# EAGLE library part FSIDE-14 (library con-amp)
AMP connector
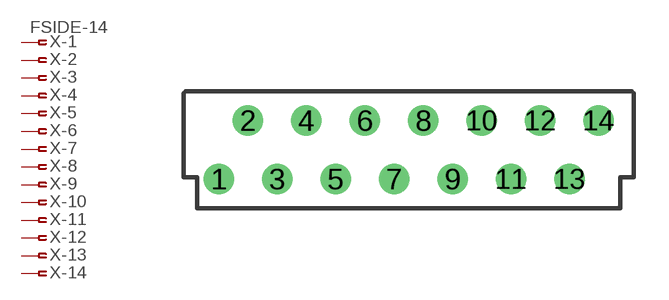
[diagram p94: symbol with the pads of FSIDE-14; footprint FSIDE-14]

Designator prefix X; gates -1=PIN-FV -2=PIN-F -3=PIN-F -4=PIN-F -5=PIN-F -6=PIN-F -7=PIN-F -8=PIN-F -9=PIN-F -10=PIN-F -11=PIN-F -12=PIN-F -13=PIN-F -14=PIN-F

## FSIDE-14 (OC_FARNELL: unknown; OC_NEWARK: unknown)  [FSIDE-14]
1  -1:1  pas
2  -2:1  pas
3  -3:1  pas
4  -4:1  pas
5  -5:1  pas
6  -6:1  pas
7  -7:1  pas
8  -8:1  pas
9  -9:1  pas
10  -10:1  pas
11  -11:1  pas
12  -12:1  pas
13  -13:1  pas
14  -14:1  pas

## Footprint FSIDE-14 (pad centres in mm)
AMP connector
drill 0.813 round: 1 -8.255,-1.27; 2 -6.985,1.27; 3 -5.715,-1.27; 4 -4.445,1.27; 5 -3.175,-1.27; 6 -1.905,1.27; 7 -0.635,-1.27; 8 0.635,1.27; 9 1.905,-1.27; 10 3.175,1.27; 11 4.445,-1.27; 12 5.715,1.27; 13 6.985,-1.27; 14 8.255,1.27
